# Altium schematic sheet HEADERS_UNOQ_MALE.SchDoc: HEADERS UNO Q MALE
size A3; Author: Silvio Navaretti; CompanyName: Arduino SRL; DrawnBy: Silvio Navaretti; Engineer: Silvio Navaretti; Organization: Arduino SRL; DocumentNumber: ASX00083; SheetNumber: 2; SheetTotal: 11; RevAuthor: Silvio Navaretti
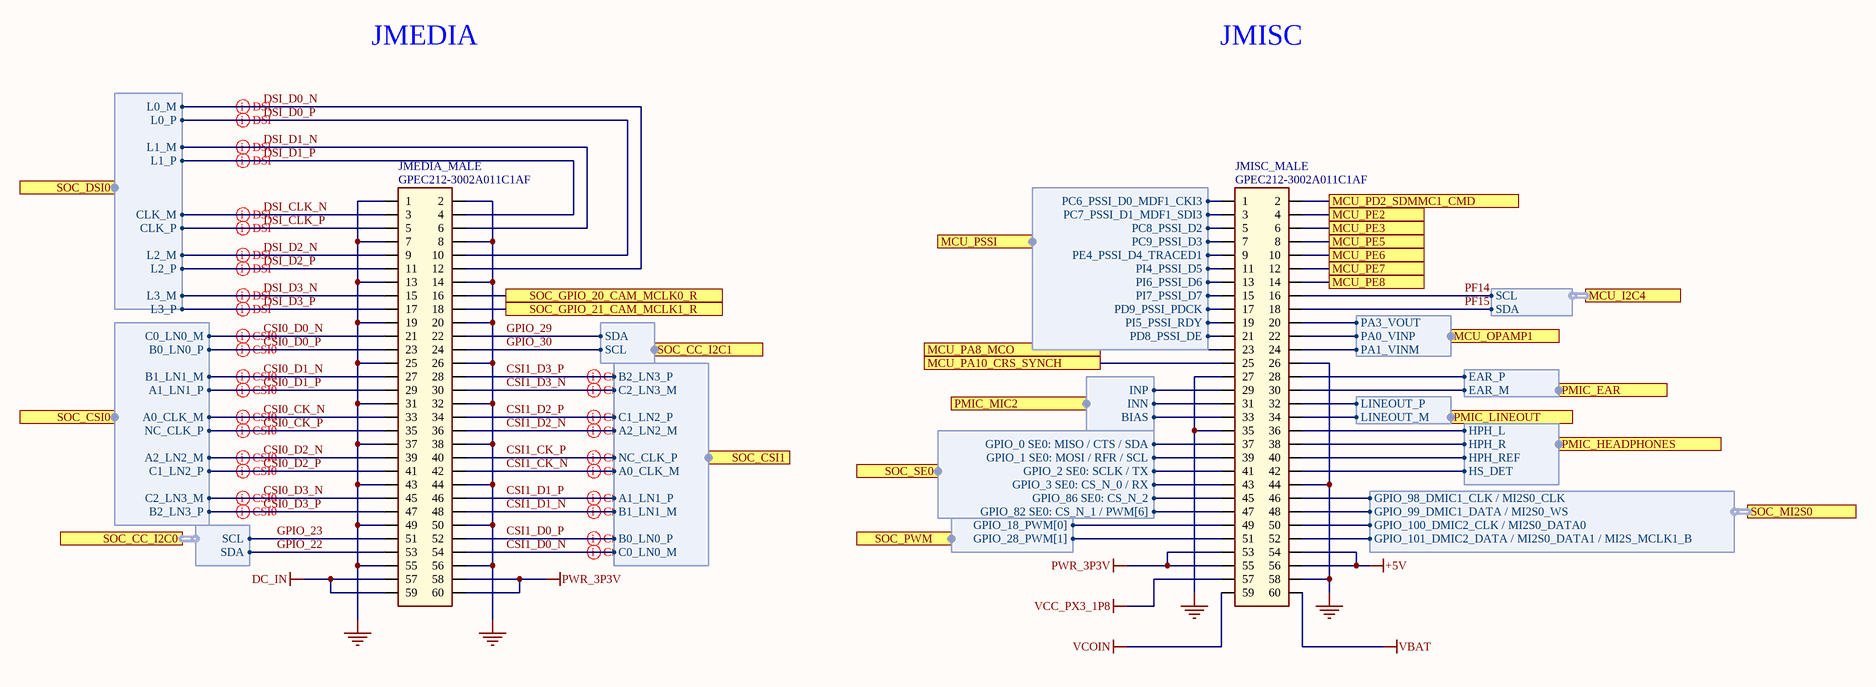
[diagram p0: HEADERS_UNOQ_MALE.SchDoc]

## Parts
JMEDIA_MALE  GPEC212-3002A011C1AF  [GPEC212-3002A011C1AF]
JMISC_MALE  GPEC212-3002A011C1AF  [GPEC212-3002A011C1AF]

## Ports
MCU_I2C4 (harness I2C), MCU_OPAMP1 (harness MCU_OPAMP), MCU_PA8_MCO, MCU_PA10_CRS_SYNCH, MCU_PD2_SDMMC1_CMD, MCU_PE2, MCU_PE3, MCU_PE5, MCU_PE6, MCU_PE7, MCU_PE8, MCU_PSSI (harness PSSI_MCU), PMIC_EAR (harness EAT), PMIC_HEADPHONES (harness HEADPHONES), PMIC_LINEOUT (harness LINEOUT), PMIC_MIC2 (harness MIC), SOC_CC_I2C0 (harness I2C), SOC_CC_I2C1 (harness I2C), SOC_CSI0 (harness IMOLA_CSI), SOC_CSI1 (harness IMOLA_CSI), SOC_DSI0 (harness IMOLA_DSI), SOC_GPIO_20_CAM_MCLK0_R, SOC_GPIO_21_CAM_MCLK1_R, SOC_MI2S0 (harness SOC_I2S), SOC_PWM (harness SOC_PWM), SOC_SE0 (harness SOC_GPIO)

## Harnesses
IMOLA_DSI: L1_P, L1_M, L3_P, L3_M, CLK_P, CLK_M, L0_P, L0_M, L2_P, L2_M
I2C: SDA, SCL
IMOLA_CSI: C2_LN3_M, A2_LN2_M, C1_LN2_P, C0_LN0_M, B0_LN0_P, A0_CLK_M, NC_CLK_P, B1_LN1_M, A1_LN1_P, B2_LN3_P
PSSI_MCU: PC6_PSSI_D0_MDF1_CKI3, PC7_PSSI_D1_MDF1_SDI3, PC8_PSSI_D2, PC9_PSSI_D3, PE4_PSSI_D4_TRACED1, PI4_PSSI_D5, PI6_PSSI_D6, PI7_PSSI_D7, PD9_PSSI_PDCK, PI5_PSSI_RDY, PD8_PSSI_DE
MCU_OPAMP: PA3_VOUT, PA0_VINP, PA1_VINM
EAT: EAR_P, EAR_M
MIC: INP, INN, BIAS
LINEOUT: LINEOUT_P, LINEOUT_M
HEADPHONES: HPH_L, HPH_R, HPH_REF, HS_DET
SOC_GPIO: GPIO_0 SE0: MISO / CTS / SDA, GPIO_1 SE0: MOSI / RFR / SCL, GPIO_2 SE0: SCLK / TX, GPIO_3 SE0: CS_N_0 / RX, GPIO_86 SE0: CS_N_2, GPIO_82 SE0: CS_N_1 / PWM[6]
SOC_I2S: GPIO_98_DMIC1_CLK / MI2S0_CLK, GPIO_99_DMIC1_DATA / MI2S0_WS, GPIO_100_DMIC2_CLK / MI2S0_DATA0, GPIO_101_DMIC2_DATA / MI2S0_DATA1 / MI2S_MCLK1_B
SOC_PWM: GPIO_18_PWM[0], GPIO_28_PWM[1]

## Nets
+5V: JMISC_MALE.54 JMISC_MALE.56
DC_IN: JMEDIA_MALE.57 JMEDIA_MALE.59
GND: JMEDIA_MALE.1 JMEDIA_MALE.2 JMEDIA_MALE.7 JMEDIA_MALE.8 JMEDIA_MALE.13 JMEDIA_MALE.14 JMEDIA_MALE.19 JMEDIA_MALE.20 JMEDIA_MALE.25 JMEDIA_MALE.26 JMEDIA_MALE.31 JMEDIA_MALE.32 JMEDIA_MALE.37 JMEDIA_MALE.38 JMEDIA_MALE.43 JMEDIA_MALE.44 JMEDIA_MALE.49 JMEDIA_MALE.50 JMEDIA_MALE.55 JMEDIA_MALE.56 JMISC_MALE.26 JMISC_MALE.27 JMISC_MALE.35 JMISC_MALE.44 JMISC_MALE.58
PWR_3P3V: JMEDIA_MALE.58 JMEDIA_MALE.60 JMISC_MALE.53 JMISC_MALE.55
VBAT: JMISC_MALE.60
VCC_PX3_1P8: JMISC_MALE.57
VCOIN: JMISC_MALE.59
CSI0_CK_N: JMEDIA_MALE.33 ; port SOC_CSI0.A0_CLK_M
CSI0_CK_P: JMEDIA_MALE.35 ; port SOC_CSI0.NC_CLK_P
CSI0_D0_N: JMEDIA_MALE.21 ; port SOC_CSI0.C0_LN0_M
CSI0_D0_P: JMEDIA_MALE.23 ; port SOC_CSI0.B0_LN0_P
CSI0_D1_N: JMEDIA_MALE.27 ; port SOC_CSI0.B1_LN1_M
CSI0_D1_P: JMEDIA_MALE.29 ; port SOC_CSI0.A1_LN1_P
CSI0_D2_N: JMEDIA_MALE.39 ; port SOC_CSI0.A2_LN2_M
CSI0_D2_P: JMEDIA_MALE.41 ; port SOC_CSI0.C1_LN2_P
CSI0_D3_N: JMEDIA_MALE.45 ; port SOC_CSI0.C2_LN3_M
CSI0_D3_P: JMEDIA_MALE.47 ; port SOC_CSI0.B2_LN3_P
CSI1_CK_N: JMEDIA_MALE.42 ; port SOC_CSI1.A0_CLK_M
CSI1_CK_P: JMEDIA_MALE.40 ; port SOC_CSI1.NC_CLK_P
CSI1_D0_N: JMEDIA_MALE.54 ; port SOC_CSI1.C0_LN0_M
CSI1_D0_P: JMEDIA_MALE.52 ; port SOC_CSI1.B0_LN0_P
CSI1_D1_N: JMEDIA_MALE.48 ; port SOC_CSI1.B1_LN1_M
CSI1_D1_P: JMEDIA_MALE.46 ; port SOC_CSI1.A1_LN1_P
CSI1_D2_N: JMEDIA_MALE.36 ; port SOC_CSI1.A2_LN2_M
CSI1_D2_P: JMEDIA_MALE.34 ; port SOC_CSI1.C1_LN2_P
CSI1_D3_N: JMEDIA_MALE.30 ; port SOC_CSI1.C2_LN3_M
CSI1_D3_P: JMEDIA_MALE.28 ; port SOC_CSI1.B2_LN3_P
DSI_CLK_N: JMEDIA_MALE.3 ; port SOC_DSI0.CLK_M
DSI_CLK_P: JMEDIA_MALE.5 ; port SOC_DSI0.CLK_P
DSI_D0_N: JMEDIA_MALE.12 ; port SOC_DSI0.L0_M
DSI_D0_P: JMEDIA_MALE.10 ; port SOC_DSI0.L0_P
DSI_D1_N: JMEDIA_MALE.6 ; port SOC_DSI0.L1_M
DSI_D1_P: JMEDIA_MALE.4 ; port SOC_DSI0.L1_P
DSI_D2_N: JMEDIA_MALE.9 ; port SOC_DSI0.L2_M
DSI_D2_P: JMEDIA_MALE.11 ; port SOC_DSI0.L2_P
DSI_D3_N: JMEDIA_MALE.15 ; port SOC_DSI0.L3_M
DSI_D3_P: JMEDIA_MALE.17 ; port SOC_DSI0.L3_P
GPIO_22: JMEDIA_MALE.53 ; port SOC_CC_I2C0.SDA
GPIO_23: JMEDIA_MALE.51 ; port SOC_CC_I2C0.SCL
GPIO_29: JMEDIA_MALE.22 ; port SOC_CC_I2C1.SDA
GPIO_30: JMEDIA_MALE.24 ; port SOC_CC_I2C1.SCL
MCU_PA8_MCO: JMISC_MALE.23 ; port MCU_PA8_MCO
MCU_PA10_CRS_SYNCH: JMISC_MALE.25 ; port MCU_PA10_CRS_SYNCH
MCU_PD2_SDMMC1_CMD: JMISC_MALE.2 ; port MCU_PD2_SDMMC1_CMD
MCU_PE2: JMISC_MALE.4 ; port MCU_PE2
MCU_PE3: JMISC_MALE.6 ; port MCU_PE3
MCU_PE5: JMISC_MALE.8 ; port MCU_PE5
MCU_PE6: JMISC_MALE.10 ; port MCU_PE6
MCU_PE7: JMISC_MALE.12 ; port MCU_PE7
MCU_PE8: JMISC_MALE.14 ; port MCU_PE8
PF14: JMISC_MALE.16 ; port MCU_I2C4.SCL
PF15: JMISC_MALE.18 ; port MCU_I2C4.SDA
SOC_GPIO_20_CAM_MCLK0_R: JMEDIA_MALE.16 ; port SOC_GPIO_20_CAM_MCLK0_R
SOC_GPIO_21_CAM_MCLK1_R: JMEDIA_MALE.18 ; port SOC_GPIO_21_CAM_MCLK1_R
NetJMISC_MALE_1: JMISC_MALE.1 ; port MCU_PSSI.PC6_PSSI_D0_MDF1_CKI3
NetJMISC_MALE_3: JMISC_MALE.3 ; port MCU_PSSI.PC7_PSSI_D1_MDF1_SDI3
NetJMISC_MALE_5: JMISC_MALE.5 ; port MCU_PSSI.PC8_PSSI_D2
NetJMISC_MALE_7: JMISC_MALE.7 ; port MCU_PSSI.PC9_PSSI_D3
NetJMISC_MALE_9: JMISC_MALE.9 ; port MCU_PSSI.PE4_PSSI_D4_TRACED1
NetJMISC_MALE_11: JMISC_MALE.11 ; port MCU_PSSI.PI4_PSSI_D5
NetJMISC_MALE_13: JMISC_MALE.13 ; port MCU_PSSI.PI6_PSSI_D6
NetJMISC_MALE_15: JMISC_MALE.15 ; port MCU_PSSI.PI7_PSSI_D7
NetJMISC_MALE_17: JMISC_MALE.17 ; port MCU_PSSI.PD9_PSSI_PDCK
NetJMISC_MALE_19: JMISC_MALE.19 ; port MCU_PSSI.PI5_PSSI_RDY
NetJMISC_MALE_20: JMISC_MALE.20 ; port MCU_OPAMP1.PA3_VOUT
NetJMISC_MALE_21: JMISC_MALE.21 ; port MCU_PSSI.PD8_PSSI_DE
NetJMISC_MALE_22: JMISC_MALE.22 ; port MCU_OPAMP1.PA0_VINP
NetJMISC_MALE_24: JMISC_MALE.24 ; port MCU_OPAMP1.PA1_VINM
NetJMISC_MALE_28: JMISC_MALE.28 ; port PMIC_EAR.EAR_P
NetJMISC_MALE_29: JMISC_MALE.29 ; port PMIC_MIC2.INP
NetJMISC_MALE_30: JMISC_MALE.30 ; port PMIC_EAR.EAR_M
NetJMISC_MALE_31: JMISC_MALE.31 ; port PMIC_MIC2.INN
NetJMISC_MALE_32: JMISC_MALE.32 ; port PMIC_LINEOUT.LINEOUT_P
NetJMISC_MALE_33: JMISC_MALE.33 ; port PMIC_MIC2.BIAS
NetJMISC_MALE_34: JMISC_MALE.34 ; port PMIC_LINEOUT.LINEOUT_M
NetJMISC_MALE_36: JMISC_MALE.36 ; port PMIC_HEADPHONES.HPH_L
NetJMISC_MALE_37: JMISC_MALE.37 ; port SOC_SE0.GPIO_0 SE0: MISO / CTS / SDA
NetJMISC_MALE_38: JMISC_MALE.38 ; port PMIC_HEADPHONES.HPH_R
NetJMISC_MALE_39: JMISC_MALE.39 ; port SOC_SE0.GPIO_1 SE0: MOSI / RFR / SCL
NetJMISC_MALE_40: JMISC_MALE.40 ; port PMIC_HEADPHONES.HPH_REF
NetJMISC_MALE_41: JMISC_MALE.41 ; port SOC_SE0.GPIO_2 SE0: SCLK / TX
NetJMISC_MALE_42: JMISC_MALE.42 ; port PMIC_HEADPHONES.HS_DET
NetJMISC_MALE_43: JMISC_MALE.43 ; port SOC_SE0.GPIO_3 SE0: CS_N_0 / RX
NetJMISC_MALE_45: JMISC_MALE.45 ; port SOC_SE0.GPIO_86 SE0: CS_N_2
NetJMISC_MALE_46: JMISC_MALE.46 ; port SOC_MI2S0.GPIO_98_DMIC1_CLK / MI2S0_CLK
NetJMISC_MALE_47: JMISC_MALE.47 ; port SOC_SE0.GPIO_82 SE0: CS_N_1 / PWM[6]
NetJMISC_MALE_48: JMISC_MALE.48 ; port SOC_MI2S0.GPIO_99_DMIC1_DATA / MI2S0_WS
NetJMISC_MALE_49: JMISC_MALE.49 ; port SOC_PWM.GPIO_18_PWM[0]
NetJMISC_MALE_50: JMISC_MALE.50 ; port SOC_MI2S0.GPIO_100_DMIC2_CLK / MI2S0_DATA0
NetJMISC_MALE_51: JMISC_MALE.51 ; port SOC_PWM.GPIO_28_PWM[1]
NetJMISC_MALE_52: JMISC_MALE.52 ; port SOC_MI2S0.GPIO_101_DMIC2_DATA / MI2S0_DATA1 / MI2S_MCLK1_B

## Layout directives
differential pair; differential pair class DSI; net class IMPEDANCE_100R: DSI_CLK_N, DSI_CLK_P, DSI_D0_N, DSI_D0_P, DSI_D1_N, DSI_D1_P, DSI_D2_N, DSI_D2_P, DSI_D3_N, DSI_D3_P
differential pair; differential pair class CSI0; net class IMPEDANCE_100R: CSI0_CK_N, CSI0_CK_P, CSI0_D0_N, CSI0_D0_P, CSI0_D1_N, CSI0_D1_P, CSI0_D2_N, CSI0_D2_P, CSI0_D3_N, CSI0_D3_P
differential pair; differential pair class CSI1; net class IMPEDANCE_100R: CSI1_CK_N, CSI1_CK_P, CSI1_D0_N, CSI1_D0_P, CSI1_D1_N, CSI1_D1_P, CSI1_D2_N, CSI1_D2_P, CSI1_D3_N, CSI1_D3_P

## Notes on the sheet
- JMEDIA
- JMISC

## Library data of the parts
JMEDIA_MALE JMISC_MALE = J0568-A.3: CONN HEADER MALE VERTICAL SMD 1.27mm 2x30 POS lead heigth 3.5mm; Manufacturer: Greenconn; Code Arduino: J0568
